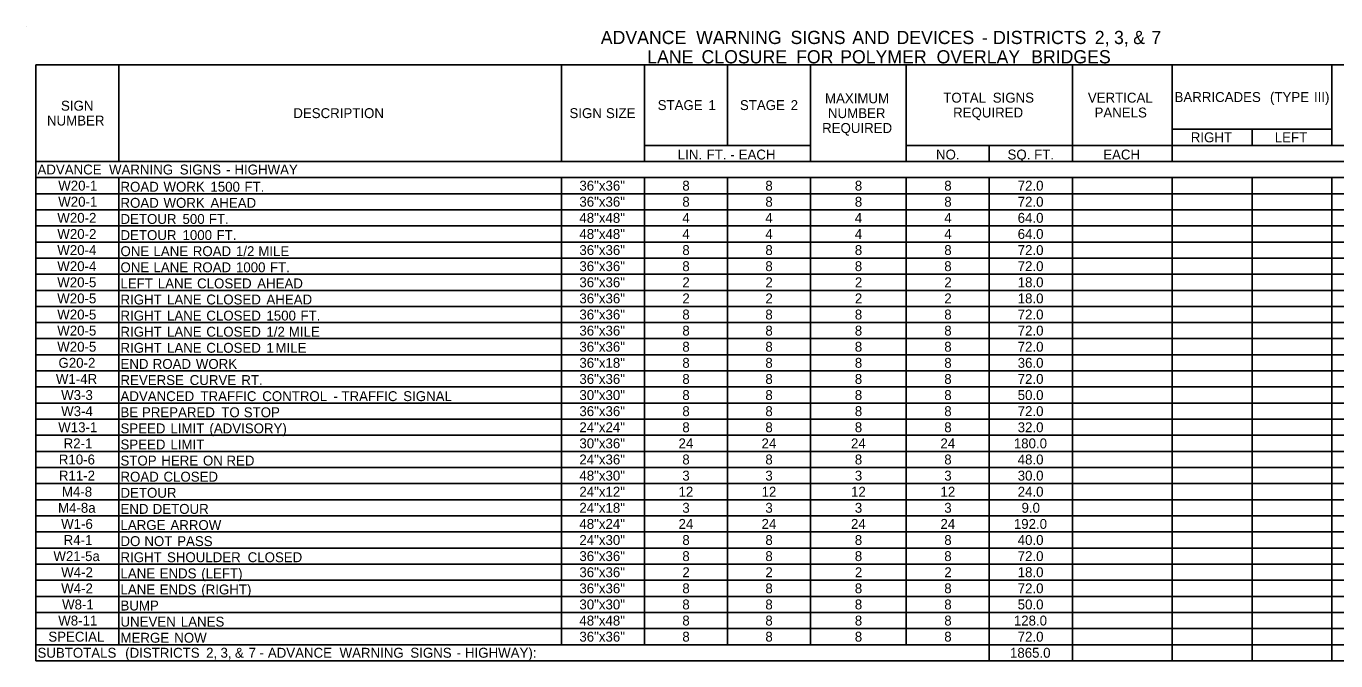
# Model space of a CAD drawing. Extents: x 544250 to 1930787, y -1948365 to 596640.
# Drawn here: x 544449 to 545241, y -1946565 to -1946181 of the extents above; entities that cross this region are included whole.
import ezdxf

# ---------------------------------------------------------------- set-up
doc = ezdxf.new("R2010")
doc.units = 0
doc.layers.add('Default', color=7, linetype='Continuous')

msp = doc.modelspace()

# ---------------------------------------------------------------- linework, layer by layer
at = {"layer": 'Default'}
for p, q in [((544448.54, -1946181.14), (544448.54, -1946181.14)), ((544454.39, -1946204.54), (545554.19, -1946204.54)), ((544454.39, -1946565.29), (544454.39, -1946204.54)), ((544454.39, -1946565.29), (544454.39, -1946204.54)), ((544504.61, -1946263.04), (544504.61, -1946204.54)), ((544772.24, -1946263.04), (544772.24, -1946204.54)), ((544822.46, -1946263.04), (544822.46, -1946204.54)), ((544872.67, -1946253.29), (544872.67, -1946204.54)), ((544922.88, -1946263.04), (544922.88, -1946204.54)), ((544980.89, -1946263.04), (544980.89, -1946204.54)), ((545081.32, -1946263.04), (545081.32, -1946204.54)), ((545141.77, -1946263.04), (545141.77, -1946204.54)), ((545238.29, -1946253.29), (545238.29, -1946204.54)), ((545141.77, -1946243.54), (545238.29, -1946243.54)), ((545190.03, -1946253.29), (545190.03, -1946243.54)), ((545190.03, -1946253.29), (545190.03, -1946243.54)), ((544822.46, -1946253.29), (544922.88, -1946253.29)), ((544922.88, -1946263.04), (544922.88, -1946253.29)), ((544980.89, -1946253.29), (545554.19, -1946253.29)), ((545031.11, -1946263.04), (545031.11, -1946253.29)), ((545141.77, -1946253.29), (545190.03, -1946253.29)), ((545141.77, -1946263.04), (545141.77, -1946253.29)), ((545190.03, -1946253.29), (545554.19, -1946253.29)), ((544454.39, -1946263.04), (545554.19, -1946263.04)), ((544922.88, -1946263.04), (545554.19, -1946263.04)), ((544454.39, -1946272.79), (545554.19, -1946272.79)), ((544504.61, -1946555.54), (544504.61, -1946272.79)), ((544504.61, -1946555.54), (544504.61, -1946272.79)), ((544772.24, -1946555.54), (544772.24, -1946272.79)), ((544772.24, -1946555.54), (544772.24, -1946272.79)), ((544822.46, -1946555.54), (544822.46, -1946272.79)), ((544822.46, -1946555.54), (544822.46, -1946272.79)), ((544872.67, -1946555.54), (544872.67, -1946272.79)), ((544872.67, -1946555.54), (544872.67, -1946272.79)), ((544922.88, -1946555.54), (544922.88, -1946272.79)), ((544922.88, -1946555.54), (544922.88, -1946272.79)), ((544980.89, -1946555.54), (544980.89, -1946272.79)), ((545031.11, -1946555.54), (545031.11, -1946272.79)), ((545031.11, -1946565.29), (545031.11, -1946272.79)), ((545081.32, -1946565.29), (545081.32, -1946272.79)), ((545081.32, -1946565.29), (545081.32, -1946272.79)), ((545141.77, -1946565.29), (545141.77, -1946272.79)), ((545141.77, -1946565.29), (545141.77, -1946272.79)), ((545190.03, -1946565.29), (545190.03, -1946272.79)), ((545190.03, -1946565.29), (545190.03, -1946272.79)), ((545238.29, -1946565.29), (545238.29, -1946272.79)), ((545238.29, -1946565.29), (545238.29, -1946272.79)), ((544454.39, -1946282.54), (545554.19, -1946282.54)), ((544454.39, -1946292.29), (545554.19, -1946292.29)), ((544454.39, -1946302.04), (545554.19, -1946302.04)), ((544454.39, -1946311.79), (545554.19, -1946311.79)), ((544454.39, -1946321.54), (545554.19, -1946321.54)), ((544454.39, -1946331.29), (545554.19, -1946331.29)), ((544454.39, -1946341.04), (545554.19, -1946341.04)), ((544454.39, -1946350.79), (545554.19, -1946350.79)), ((544454.39, -1946360.54), (545554.19, -1946360.54)), ((544454.39, -1946370.29), (545554.19, -1946370.29)), ((544454.39, -1946380.04), (545554.19, -1946380.04)), ((544454.39, -1946389.79), (545554.19, -1946389.79)), ((544454.39, -1946399.54), (545554.19, -1946399.54)), ((544454.39, -1946409.29), (545554.19, -1946409.29)), ((544454.39, -1946419.04), (545554.19, -1946419.04)), ((544454.39, -1946428.79), (545554.19, -1946428.79)), ((544454.39, -1946438.54), (545554.19, -1946438.54)), ((544454.39, -1946448.29), (545554.19, -1946448.29)), ((544454.39, -1946458.04), (545554.19, -1946458.04)), ((544454.39, -1946467.79), (545554.19, -1946467.79)), ((544454.39, -1946477.54), (545554.19, -1946477.54)), ((544454.39, -1946487.29), (545554.19, -1946487.29)), ((544454.39, -1946497.04), (545554.19, -1946497.04)), ((544454.39, -1946506.79), (545554.19, -1946506.79)), ((544454.39, -1946516.54), (545554.19, -1946516.54)), ((544454.39, -1946526.29), (545554.19, -1946526.29)), ((544454.39, -1946536.04), (545554.19, -1946536.04)), ((544454.39, -1946545.79), (545554.19, -1946545.79)), ((544454.39, -1946555.54), (545554.19, -1946555.54)), ((544454.39, -1946555.54), (545554.19, -1946555.54)), ((544454.39, -1946565.29), (545554.19, -1946565.29))]:
    msp.add_line(p, q, dxfattribs=at)

# ---------------------------------------------------------------- texts
for s, height, p in [('ADVANCE', 8, (544796.1, -1946191.97)), (' WARNING', 8, (544850.82, -1946191.97)), (' SIGNS', 8, (544907.89, -1946191.97)), (' AND', 8, (544945.23, -1946191.97)), (' DEVICES', 8, (544972, -1946191.97)), (' -', 8, (545023.63, -1946191.97)), (' DISTRICTS', 8, (545030.38, -1946191.97)), (' 2,', 8, (545091.93, -1946191.97)), (' 3,', 8, (545103.55, -1946191.97)), (' &', 8, (545115.16, -1946191.97)), (' 7', 8, (545126.16, -1946191.97)), ('LANE', 8, (544824.18, -1946203.67)), (' CLOSURE', 8, (544854.06, -1946203.67)), (' FOR', 8, (544911.27, -1946203.67)), (' POLYMER', 8, (544937.91, -1946203.67)), (' OVERLAY', 8, (544996.24, -1946203.67)), (' BRIDGES', 8, (545053.41, -1946203.67)), ('BARRICADES', 6, (545143.15, -1946227.04)), (' (TYPE', 6, (545198.64, -1946227.04)), (' III)', 6, (545225.24, -1946227.04)), ('SIGN', 6, (544469.59, -1946232.29)), ('STAGE', 6, (544830.51, -1946231.92)), (' 1', 6, (544858.98, -1946231.92)), ('STAGE', 6, (544880.26, -1946231.92)), (' 2', 6, (544908.73, -1946231.92)), ('MAXIMUM', 6, (544931.7, -1946227.79)), ('TOTAL', 6, (545003.26, -1946227.42)), (' SIGNS', 6, (545030.95, -1946227.42)), ('VERTICAL', 6, (545090.71, -1946227.42)), ('NUMBER', 6, (544461.12, -1946241.29)), ('DESCRIPTION', 6, (544610.11, -1946236.79)), ('SIGN', 6, (544777.16, -1946236.79)), (' SIZE', 6, (544796.99, -1946236.79)), ('NUMBER', 6, (544933.51, -1946236.79)), ('REQUIRED', 6, (545009.19, -1946236.42)), ('PANELS', 6, (545094.74, -1946236.42)), ('REQUIRED', 6, (544929.97, -1946245.79)), ('RIGHT', 6, (545152.95, -1946251.42)), ('LEFT', 6, (545203.77, -1946251.42)), ('LIN.', 6, (544842.63, -1946261.84)), (' FT.', 6, (544857.89, -1946261.84)), (' -', 6, (544872.21, -1946261.84)), (' EACH', 6, (544877.27, -1946261.84)), ('NO.', 6, (544998.84, -1946261.84)), ('SQ.', 6, (545042.12, -1946261.84)), (' FT.', 6, (545055.98, -1946261.84)), ('EACH', 6, (545099.99, -1946261.84)), ('ADVANCE', 6, (544455.37, -1946270.92)), (' WARNING', 6, (544496.41, -1946270.92)), (' SIGNS', 6, (544539.21, -1946270.92)), (' -', 6, (544567.22, -1946270.92)), (' HIGHWAY', 6, (544572.28, -1946270.92)), ('W20-1', 6, (544467.93, -1946280.67)), ('ROAD', 6, (544505.58, -1946281.34)), (' WORK', 6, (544529.36, -1946281.34)), (' 1500', 6, (544557.75, -1946281.34)), (' FT.', 6, (544578.31, -1946281.34)), ('36"x36"', 6, (544783.15, -1946280.67)), ('8', 6, (544845.42, -1946280.67)), ('8', 6, (544895.63, -1946280.67)), ('8', 6, (544949.74, -1946280.67)), ('8', 6, (545003.86, -1946280.67)), ('72.0', 6, (545048.26, -1946280.67)), ('W20-1', 6, (544467.93, -1946290.42)), ('36"x36"', 6, (544783.15, -1946290.42)), ('8', 6, (544845.42, -1946290.42)), ('8', 6, (544895.63, -1946290.42)), ('8', 6, (544949.74, -1946290.42)), ('8', 6, (545003.86, -1946290.42)), ('72.0', 6, (545048.26, -1946290.42)), ('ROAD', 6, (544505.58, -1946291.09)), (' WORK', 6, (544529.36, -1946291.09)), (' AHEAD', 6, (544557.75, -1946291.09)), ('W20-2', 6, (544467.38, -1946300.17)), ('DETOUR', 6, (544505.58, -1946300.84)), (' 500', 6, (544540.87, -1946300.84)), (' FT.', 6, (544556.77, -1946300.84)), ('48"x48"', 6, (544783.15, -1946300.17)), ('4', 6, (544845.44, -1946300.17)), ('4', 6, (544895.65, -1946300.17)), ('4', 6, (544949.76, -1946300.17)), ('4', 6, (545003.87, -1946300.17)), ('64.0', 6, (545048.26, -1946300.17)), ('W20-2', 6, (544467.38, -1946309.92)), ('DETOUR', 6, (544505.58, -1946310.59)), (' 1000', 6, (544540.87, -1946310.59)), (' FT.', 6, (544561.43, -1946310.59)), ('48"x48"', 6, (544783.15, -1946309.92)), ('4', 6, (544845.44, -1946309.92)), ('4', 6, (544895.65, -1946309.92)), ('4', 6, (544949.76, -1946309.92)), ('4', 6, (545003.87, -1946309.92)), ('64.0', 6, (545048.26, -1946309.92)), ('W20-4', 6, (544467.36, -1946319.67)), ('ONE', 6, (544505.58, -1946320.34)), (' LANE', 6, (544523.3, -1946320.34)), (' ROAD', 6, (544547.08, -1946320.34)), (' 1/2', 6, (544573.19, -1946320.34)), (' MILE', 6, (544586.72, -1946320.34)), ('36"x36"', 6, (544783.15, -1946319.67)), ('8', 6, (544845.42, -1946319.67)), ('8', 6, (544895.63, -1946319.67)), ('8', 6, (544949.74, -1946319.67)), ('8', 6, (545003.86, -1946319.67)), ('72.0', 6, (545048.26, -1946319.67)), ('W20-4', 6, (544467.36, -1946329.42)), ('ONE', 6, (544505.58, -1946330.09)), (' LANE', 6, (544523.3, -1946330.09)), (' ROAD', 6, (544547.08, -1946330.09)), (' 1000', 6, (544573.19, -1946330.09)), (' FT.', 6, (544593.75, -1946330.09)), ('36"x36"', 6, (544783.15, -1946329.42)), ('8', 6, (544845.42, -1946329.42)), ('8', 6, (544895.63, -1946329.42)), ('8', 6, (544949.74, -1946329.42)), ('8', 6, (545003.86, -1946329.42)), ('72.0', 6, (545048.26, -1946329.42)), ('W20-5', 6, (544467.33, -1946339.17)), ('LEFT', 6, (544505.58, -1946339.84)), (' LANE', 6, (544525.91, -1946339.84)), (' CLOSED', 6, (544549.69, -1946339.84)), (' AHEAD', 6, (544586.05, -1946339.84)), ('36"x36"', 6, (544783.15, -1946339.17)), ('2', 6, (544845.45, -1946339.17)), ('2', 6, (544895.67, -1946339.17)), ('2', 6, (544949.78, -1946339.17)), ('2', 6, (545003.89, -1946339.17)), ('18.0', 6, (545048.26, -1946339.17)), ('W20-5', 6, (544467.33, -1946348.92)), ('RIGHT', 6, (544505.58, -1946349.59)), (' LANE', 6, (544531.49, -1946349.59)), (' CLOSED', 6, (544555.27, -1946349.59)), (' AHEAD', 6, (544591.63, -1946349.59)), ('36"x36"', 6, (544783.15, -1946348.92)), ('2', 6, (544845.45, -1946348.92)), ('2', 6, (544895.67, -1946348.92)), ('2', 6, (544949.78, -1946348.92)), ('2', 6, (545003.89, -1946348.92)), ('18.0', 6, (545048.26, -1946348.92)), ('W20-5', 6, (544467.33, -1946358.67)), ('RIGHT', 6, (544505.58, -1946359.34)), (' LANE', 6, (544531.49, -1946359.34)), (' CLOSED', 6, (544555.27, -1946359.34)), (' 1500', 6, (544591.63, -1946359.34)), (' FT.', 6, (544612.2, -1946359.34)), ('36"x36"', 6, (544783.15, -1946358.67)), ('8', 6, (544845.42, -1946358.67)), ('8', 6, (544895.63, -1946358.67)), ('8', 6, (544949.74, -1946358.67)), ('8', 6, (545003.86, -1946358.67)), ('72.0', 6, (545048.26, -1946358.67)), ('W20-5', 6, (544467.33, -1946368.42)), ('RIGHT', 6, (544505.58, -1946369.09)), (' LANE', 6, (544531.49, -1946369.09)), (' CLOSED', 6, (544555.27, -1946369.09)), (' 1/2', 6, (544591.63, -1946369.09)), (' MILE', 6, (544605.16, -1946369.09)), ('36"x36"', 6, (544783.15, -1946368.42)), ('8', 6, (544845.42, -1946368.42)), ('8', 6, (544895.63, -1946368.42)), ('8', 6, (544949.74, -1946368.42)), ('8', 6, (545003.86, -1946368.42)), ('72.0', 6, (545048.26, -1946368.42)), ('W20-5', 6, (544467.33, -1946378.17)), ('RIGHT', 6, (544505.58, -1946378.84)), (' LANE', 6, (544531.49, -1946378.84)), (' CLOSED', 6, (544555.27, -1946378.84)), (' 1', 6, (544591.63, -1946378.84)), (' MILE', 6, (544597.08, -1946378.84)), ('36"x36"', 6, (544783.15, -1946378.17)), ('8', 6, (544845.42, -1946378.17)), ('8', 6, (544895.63, -1946378.17)), ('8', 6, (544949.74, -1946378.17)), ('8', 6, (545003.86, -1946378.17)), ('72.0', 6, (545048.26, -1946378.17)), ('G20-2', 6, (544468.08, -1946387.92)), ('END', 6, (544505.58, -1946388.59)), (' ROAD', 6, (544522.84, -1946388.59)), (' WORK', 6, (544548.94, -1946388.59)), ('36"x18"', 6, (544783.15, -1946387.92)), ('8', 6, (544845.42, -1946387.92)), ('8', 6, (544895.63, -1946387.92)), ('8', 6, (544949.74, -1946387.92)), ('8', 6, (545003.86, -1946387.92)), ('36.0', 6, (545048.26, -1946387.92)), ('W1-4R', 6, (544466.52, -1946397.67)), ('REVERSE', 6, (544505.58, -1946398.34)), (' CURVE', 6, (544545.21, -1946398.34)), (' RT.', 6, (544576.44, -1946398.34)), ('36"x36"', 6, (544783.15, -1946397.67)), ('8', 6, (544845.42, -1946397.67)), ('8', 6, (544895.63, -1946397.67)), ('8', 6, (544949.74, -1946397.67)), ('8', 6, (545003.86, -1946397.67)), ('72.0', 6, (545048.26, -1946397.67)), ('W3-3', 6, (544469.68, -1946407.42)), ('ADVANCED', 6, (544505.58, -1946408.09)), (' TRAFFIC', 6, (544551.72, -1946408.09)), (' CONTROL', 6, (544589.11, -1946408.09)), (' TRAFFIC', 6, (544636.99, -1946408.09)), (' SIGNAL', 6, (544674.38, -1946408.09)), ('30"x30"', 6, (544783.15, -1946407.42)), ('8', 6, (544845.42, -1946407.42)), ('8', 6, (544895.63, -1946407.42)), ('8', 6, (544949.74, -1946407.42)), ('8', 6, (545003.86, -1946407.42)), ('50.0', 6, (545048.26, -1946407.42)), ('W3-4', 6, (544469.69, -1946417.17)), (' -', 6, (544632.13, -1946408.09)), ('36"x36"', 6, (544783.15, -1946417.17)), ('8', 6, (544845.42, -1946417.17)), ('8', 6, (544895.63, -1946417.17)), ('8', 6, (544949.74, -1946417.17)), ('8', 6, (545003.86, -1946417.17)), ('72.0', 6, (545048.26, -1946417.17)), ('BE', 6, (544505.58, -1946417.84)), (' PREPARED', 6, (544516.32, -1946417.84)), (' TO', 6, (544564.33, -1946417.84)), (' STOP', 6, (544577.92, -1946417.84)), ('W13-1', 6, (544467.93, -1946426.92)), ('SPEED', 6, (544505.58, -1946427.59)), (' LIMIT', 6, (544533.56, -1946427.59)), (' (ADVISORY)', 6, (544557.14, -1946427.59)), ('24"x24"', 6, (544783.15, -1946426.92)), ('8', 6, (544845.42, -1946426.92)), ('8', 6, (544895.63, -1946426.92)), ('8', 6, (544949.74, -1946426.92)), ('8', 6, (545003.86, -1946426.92)), ('32.0', 6, (545048.26, -1946426.92)), ('R2-1', 6, (544471.19, -1946436.67)), ('SPEED', 6, (544505.58, -1946437.34)), (' LIMIT', 6, (544533.56, -1946437.34)), ('30"x36"', 6, (544783.15, -1946436.67)), ('24', 6, (544843.11, -1946436.67)), ('24', 6, (544893.32, -1946436.67)), ('24', 6, (544947.43, -1946436.67)), ('24', 6, (545001.54, -1946436.67)), ('180.0', 6, (545045.93, -1946436.67)), ('R10-6', 6, (544468.28, -1946446.42)), ('STOP', 6, (544505.58, -1946447.09)), (' HERE', 6, (544528.04, -1946447.09)), (' ON', 6, (544553.22, -1946447.09)), (' RED', 6, (544567.44, -1946447.09)), ('24"x36"', 6, (544783.15, -1946446.42)), ('8', 6, (544845.42, -1946446.42)), ('8', 6, (544895.63, -1946446.42)), ('8', 6, (544949.74, -1946446.42)), ('8', 6, (545003.86, -1946446.42)), ('48.0', 6, (545048.26, -1946446.42)), ('R11-2', 6, (544468.31, -1946456.17)), ('ROAD', 6, (544505.58, -1946456.84)), (' CLOSED', 6, (544529.36, -1946456.84)), ('48"x30"', 6, (544783.15, -1946456.17)), ('3', 6, (544845.42, -1946456.17)), ('3', 6, (544895.63, -1946456.17)), ('3', 6, (544949.75, -1946456.17)), ('3', 6, (545003.86, -1946456.17)), ('30.0', 6, (545048.26, -1946456.17)), ('M4-8', 6, (544470.14, -1946465.92)), ('DETOUR', 6, (544505.58, -1946466.59)), ('24"x12"', 6, (544783.15, -1946465.92)), ('12', 6, (544843.12, -1946465.92)), ('12', 6, (544893.34, -1946465.92)), ('12', 6, (544947.45, -1946465.92)), ('12', 6, (545001.56, -1946465.92)), ('24.0', 6, (545048.26, -1946465.92)), ('M4-8a', 6, (544467.8, -1946475.67)), ('END', 6, (544505.58, -1946476.34)), (' DETOUR', 6, (544522.84, -1946476.34)), ('24"x18"', 6, (544783.15, -1946475.67)), ('3', 6, (544845.42, -1946475.67)), ('3', 6, (544895.63, -1946475.67)), ('3', 6, (544949.75, -1946475.67)), ('3', 6, (545003.86, -1946475.67)), ('9.0', 6, (545050.59, -1946475.67)), ('W1-6', 6, (544469.68, -1946485.42)), ('LARGE', 6, (544505.58, -1946486.09)), (' ARROW', 6, (544533.56, -1946486.09)), ('48"x24"', 6, (544783.15, -1946485.42)), ('24', 6, (544843.11, -1946485.42)), ('24', 6, (544893.32, -1946485.42)), ('24', 6, (544947.43, -1946485.42)), ('24', 6, (545001.54, -1946485.42)), ('192.0', 6, (545045.93, -1946485.42)), ('R4-1', 6, (544471.19, -1946495.17)), ('DO', 6, (544505.58, -1946495.84)), (' NOT', 6, (544517.78, -1946495.84)), (' PASS', 6, (544537.64, -1946495.84)), ('24"x30"', 6, (544783.15, -1946495.17)), ('8', 6, (544845.42, -1946495.17)), ('8', 6, (544895.63, -1946495.17)), ('8', 6, (544949.74, -1946495.17)), ('8', 6, (545003.86, -1946495.17)), ('40.0', 6, (545048.26, -1946495.17)), ('W21-5a', 6, (544465.01, -1946504.92)), ('RIGHT', 6, (544505.58, -1946505.59)), (' SHOULDER', 6, (544531.49, -1946505.59)), (' CLOSED', 6, (544580.29, -1946505.59)), ('36"x36"', 6, (544783.15, -1946504.92)), ('8', 6, (544845.42, -1946504.92)), ('8', 6, (544895.63, -1946504.92)), ('8', 6, (544949.74, -1946504.92)), ('8', 6, (545003.86, -1946504.92)), ('72.0', 6, (545048.26, -1946504.92)), ('W4-2', 6, (544469.71, -1946514.67)), ('LANE', 6, (544505.58, -1946515.34)), (' ENDS', 6, (544527.03, -1946515.34)), (' (LEFT)', 6, (544552.22, -1946515.34)), ('36"x36"', 6, (544783.15, -1946514.67)), ('2', 6, (544845.45, -1946514.67)), ('2', 6, (544895.67, -1946514.67)), ('2', 6, (544949.78, -1946514.67)), ('2', 6, (545003.89, -1946514.67)), ('18.0', 6, (545048.26, -1946514.67)), ('W4-2', 6, (544469.71, -1946524.42)), ('LANE', 6, (544505.58, -1946525.09)), (' ENDS', 6, (544527.03, -1946525.09)), (' (RIGHT)', 6, (544552.22, -1946525.09)), ('36"x36"', 6, (544783.15, -1946524.42)), ('8', 6, (544845.42, -1946524.42)), ('8', 6, (544895.63, -1946524.42)), ('8', 6, (544949.74, -1946524.42)), ('8', 6, (545003.86, -1946524.42)), ('72.0', 6, (545048.26, -1946524.42)), ('W8-1', 6, (544470.26, -1946534.17)), ('BUMP', 6, (544505.58, -1946534.84)), ('30"x30"', 6, (544783.15, -1946534.17)), ('8', 6, (544845.42, -1946534.17)), ('8', 6, (544895.63, -1946534.17)), ('8', 6, (544949.74, -1946534.17)), ('8', 6, (545003.86, -1946534.17)), ('50.0', 6, (545048.26, -1946534.17)), ('W8-11', 6, (544467.93, -1946543.92)), ('48"x48"', 6, (544783.15, -1946543.92)), ('8', 6, (544845.42, -1946543.92)), ('8', 6, (544895.63, -1946543.92)), ('8', 6, (544949.74, -1946543.92)), ('8', 6, (545003.86, -1946543.92)), ('128.0', 6, (545045.93, -1946543.92)), ('UNEVEN', 6, (544505.58, -1946544.59)), (' LANES', 6, (544539.84, -1946544.59)), ('SPECIAL', 6, (544461.94, -1946553.67)), ('MERGE', 6, (544505.58, -1946554.34)), (' NOW', 6, (544535.88, -1946554.34)), ('36"x36"', 6, (544783.15, -1946553.67)), ('8', 6, (544845.42, -1946553.67)), ('8', 6, (544895.63, -1946553.67)), ('8', 6, (544949.74, -1946553.67)), ('8', 6, (545003.86, -1946553.67)), ('72.0', 6, (545048.26, -1946553.67)), ('SUBTOTALS', 6, (544455.37, -1946563.42)), (' (DISTRICTS', 6, (544506.19, -1946563.42)), (' 2,', 6, (544555.15, -1946563.42)), (' 3,', 6, (544563.86, -1946563.42)), (' &', 6, (544572.57, -1946563.42)), (' 7', 6, (544580.82, -1946563.42)), (' -', 6, (544587.44, -1946563.42)), (' ADVANCE', 6, (544592.5, -1946563.42)), (' WARNING', 6, (544635.87, -1946563.42)), (' SIGNS', 6, (544678.67, -1946563.42)), (' -', 6, (544706.67, -1946563.42)), (' HIGHWAY):', 6, (544711.73, -1946563.42)), ('1865.0', 6, (545043.6, -1946563.42))]:
    msp.add_text(s, height=height, dxfattribs=at).set_placement(p)

doc.saveas('drawing.dxf')
